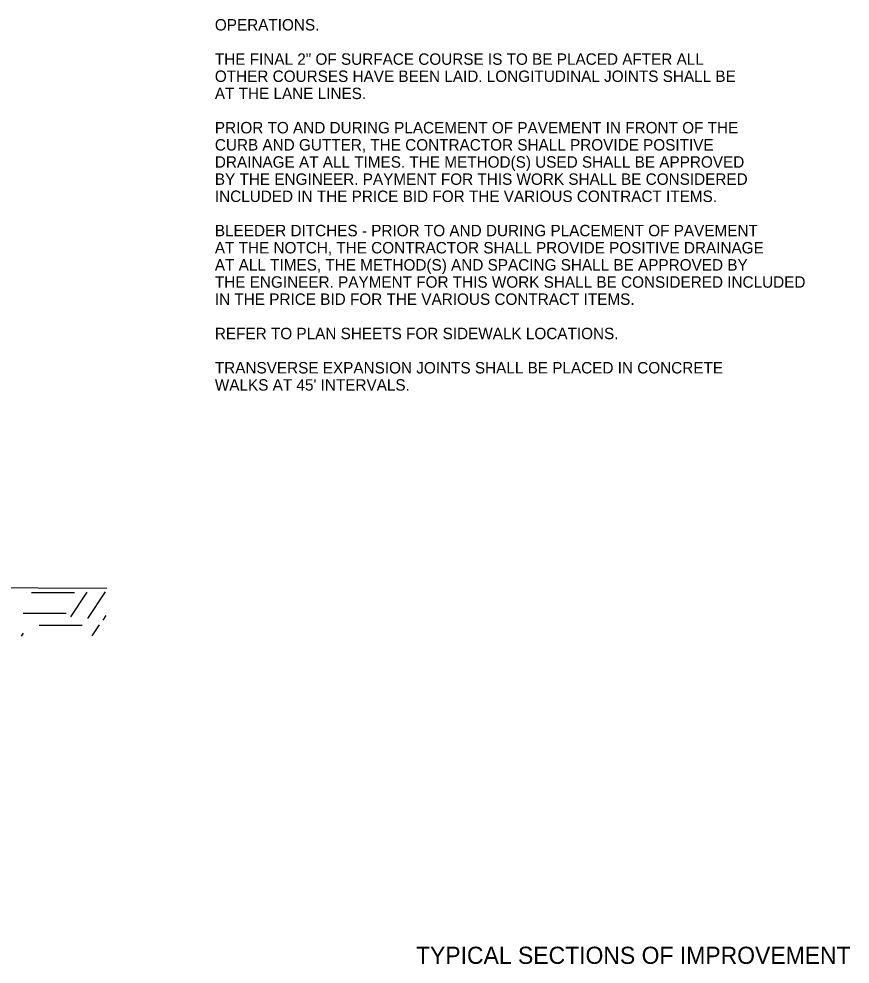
# Model space of a CAD drawing. Extents: x 1001270 to 1003428, y 1840152 to 1842912.
# Drawn here: x 1001382.52 to 1001426.13, y 1841127.4 to 1841177 of the extents above; entities that cross this region are included whole.
import ezdxf

# ---------------------------------------------------------------- set-up
doc = ezdxf.new("R2010")
doc.units = 0
doc.layers.add('19', color=7, linetype='Continuous')
doc.layers.add('60', color=7, linetype='Continuous')

msp = doc.modelspace()

# ---------------------------------------------------------------- linework, layer by layer
at = {"layer": '19'}
for p, q in [((1001385.446, 1841146.875), (1001383.184, 1841146.88)), ((1001386.092, 1841146.923), (1001385.231, 1841145.631)), ((1001387.045, 1841146.928), (1001386.121, 1841145.543)), ((1001385.007, 1841145.796), (1001382.745, 1841145.802)), ((1001387.073, 1841145.685), (1001386.919, 1841145.455)), ((1001385.845, 1841145.17), (1001383.583, 1841145.176)), ((1001386.735, 1841145.212), (1001386.347, 1841144.63)), ((1001382.751, 1841144.764), (1001382.648, 1841144.609))]:
    msp.add_line(p, q, dxfattribs=at)
msp.add_lwpolyline([(1001315.599, 1841149.903), (1001328.757, 1841149.788), (1001332.389, 1841148.179), (1001337.869, 1841149.647), (1001341.339, 1841150.613), (1001351.342, 1841150.707), (1001361.339, 1841150.529), (1001363.401, 1841150.037), (1001367.452, 1841148.739), (1001370.661, 1841147.834), (1001375.073, 1841147.083), (1001376.322, 1841147.189), (1001387.129, 1841147.132)], dxfattribs=at)

# ---------------------------------------------------------------- texts
for s, p in [('OPERATIONS. ', (1001392.802, 1841176.395)), ('THE FINAL 2" OF SURFACE COURSE IS TO BE PLACED AFTER ALL', (1001392.802, 1841174.595)), ('OTHER COURSES HAVE BEEN LAID. LONGITUDINAL JOINTS SHALL BE', (1001392.802, 1841173.695)), ('AT THE LANE LINES.', (1001392.802, 1841172.795)), ('PRIOR TO AND DURING PLACEMENT OF PAVEMENT IN FRONT OF THE', (1001392.802, 1841170.995)), ('CURB AND GUTTER, THE CONTRACTOR SHALL PROVIDE POSITIVE', (1001392.802, 1841170.095)), ('DRAINAGE AT ALL TIMES. THE METHOD(S) USED SHALL BE APPROVED', (1001392.802, 1841169.195)), ('BY THE ENGINEER. PAYMENT FOR THIS WORK SHALL BE CONSIDERED', (1001392.802, 1841168.295)), ('INCLUDED IN THE PRICE BID FOR THE VARIOUS CONTRACT ITEMS.', (1001392.802, 1841167.395)), ('BLEEDER DITCHES - PRIOR TO AND DURING PLACEMENT OF PAVEMENT', (1001392.802, 1841165.595)), ('AT THE NOTCH, THE CONTRACTOR SHALL PROVIDE POSITIVE DRAINAGE', (1001392.802, 1841164.695)), ('AT ALL TIMES, THE METHOD(S) AND SPACING SHALL BE APPROVED BY', (1001392.802, 1841163.795)), ('THE ENGINEER. PAYMENT FOR THIS WORK SHALL BE CONSIDERED INCLUDED', (1001392.802, 1841162.895)), ('IN THE PRICE BID FOR THE VARIOUS CONTRACT ITEMS.', (1001392.802, 1841161.995)), ('REFER TO PLAN SHEETS FOR SIDEWALK LOCATIONS.', (1001392.802, 1841160.195)), ('TRANSVERSE EXPANSION JOINTS SHALL BE PLACED IN CONCRETE', (1001392.802, 1841158.395)), ("WALKS AT 45' INTERVALS.", (1001392.802, 1841157.495))]:
    msp.add_text(s, height=0.6, dxfattribs=at).set_placement(p)
at = {"layer": '60'}
msp.add_text('TYPICAL SECTIONS OF IMPROVEMENT', height=0.9, dxfattribs=at).set_placement((1001403.354, 1841127.411))

doc.saveas('drawing.dxf')
